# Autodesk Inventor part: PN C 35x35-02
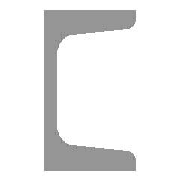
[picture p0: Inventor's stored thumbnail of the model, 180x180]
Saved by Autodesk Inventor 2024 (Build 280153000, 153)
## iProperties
IsCustomPart: 1
_CCFamilyMember: 10
_CCFamilyDisplayName: PN-86/H-93403 - Ceownik
_FrameMemberDoc: Frame Member File
_Version: 15.0.0
Created: 2023-03
Part Number: PN C 35x35-02
Material: Ogólny
Description: Ceownik
Document SubType Name: Modeling
Standard: PN-86/H-93403
Designer: Andrzej Jaskulski
Standards Organization: PN
Language: pl-PL
Size Designation: C 35x35
Categories: <MemberInstance><Categories><Category DisplayName="Kształtowniki konstrukcyjne" InternalName="089c4875-fa83-4c05-b084-43b9cc11f5ed" Mnemonic="GRDR"><CategoryPar
Stock Number: C 35x35
Density: 1 g/cm^3
Appearance: Domyślna
Checked By: A.J.
Engr Approved By: Andrzej Jaskulski
Mfg Approved By: Andrzej Jaskulski
Authority: A.J.
Company: ATC
G_L: 160,000 mm
G_W: 35,000 mm
G_H: 35,000 mm
+78594D8E-C42A-4ECC-B0AF-A7D280CED65D+CUTDETAIL1: Połączenie narożne
Author: Andrzej Jaskulski
Title: A.J.: Kurs R2024-MEP
Revision Number: 1/24
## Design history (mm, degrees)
node "Płaszczyzna początkowa"
node "Płaszczyzna końcowa"
sketch "Szkic"
  geometry: L1 (0, 0)-(0, 17.5); L2 (0, 17.5)-(35, 17.5); L3 (35, 17.5)-(35, 15.47); L4 (32.239, 12.479)-(10.522, 10.742); L5 (5, 4.761)-(5, 0); L6 (5, 0)-(0, 0); L7 (20, 17.5)-(20, 11.5); L8 (35, 12.7)-(35, 11.5); L9 (35, 11.5)-(20, 11.5); L10 (0, 15)-(0, -27); L11 (-5.539, 0)-(16.007, 0); L12 (0, 0)-(0, -17.5); L13 (0, -17.5)-(35, -17.5); L14 (35, -17.5)-(35, -15.47); L15 (32.239, -12.479)-(10.522, -10.742); L16 (5, -4.761)-(5, 0); L17 (0, 26.4)-(0, -35.9) reference; L18 (-13.764, 0)-(43.809, 0) reference; A1 r 6 centre (11, 4.761) between (10.522, 10.742) and (5, 4.761); A2 r 6 centre (11, -4.761) between (5, -4.761) and (10.522, -10.742); A3 r 3 centre (32, 15.47) between (32.239, 12.479) and (35, 15.47); A4 r 3 centre (32, -15.47) between (35, -15.47) and (32.239, -12.479); 5 further points
  constraints: 32 end point, 12 point on line, 8 point on circle, 8 tangent, 6 symmetric about line, 4 centre point, 4 parallel, 3 collinear, 3 perpendicular, 2 equal radius, 5 other
  dimensions: "d0" = 5 distance between parallel lines of L1 L5 (= G_T); "d1" = 17.5 distance between parallel lines of L6 L2 (= 0.5 x G_H); "d2" = 35 distance between parallel lines of L3 L1 (= G_W); "d3" = 6 distance of L2.end L8.end (= G_T1); "d4" = 15 distance of L7.start L2.end (= G_C); "d5" = 1.2 distance of L8.start L8.end (computed from G_NG, G_C); "d23" = 6 radius of A1 (= G_IR); "d24" = 3 radius of A3 (= G_ER); "d25" = 0 distance between parallel lines of L10 L12 (computed from ex)
extrude "Bryła" new body sketch "Szkic" stored distance "d6" = 160 (= G_L); taper "d7" = 0 deg
node "Driven Length"
  sketch "Sketch3"
    geometry: L1 (0, 0)-(10, 0) reference
    constraints: 2 end point, 1 horizontal
  workplane "Work Plane3"
node "Płaszczyzna konstrukcyjna4"
feature "Podział1"
body "Solid1"
sketch "Sketch4"
  geometry: L1 (-2, 0)-(12, 0) reference; L2 (-2, 160)-(12, 160) reference
  dimensions: "d29" = 160 distance between parallel lines of L1 L2 (derived)
other parameters: "G_W" = 35 [user parameter; used in 1 equation term], "G_H" = 35 [user parameter; used in 1 equation term], "G_T" = 5 [user parameter; used in 1 equation term], "G_T1" = 6 [user parameter; used in 1 equation term], "G_NG" = 0.8 [user parameter; used in 1 equation term], "G_ER" = 3 [user parameter; used in 1 equation term], "G_IR" = 6 [user parameter; used in 1 equation term], "G_C" = 15 [user parameter; used in 2 equation terms], "G_L" = 160 (= d29) [user parameter; used in 1 equation term], "ex" = 0 [user parameter; used in 1 equation term], "G_OFFSET_START" = 0 [user parameter; used in 1 equation term], "d26" = 0 (computed from G_OFFSET_START), "d28" = 90 deg
